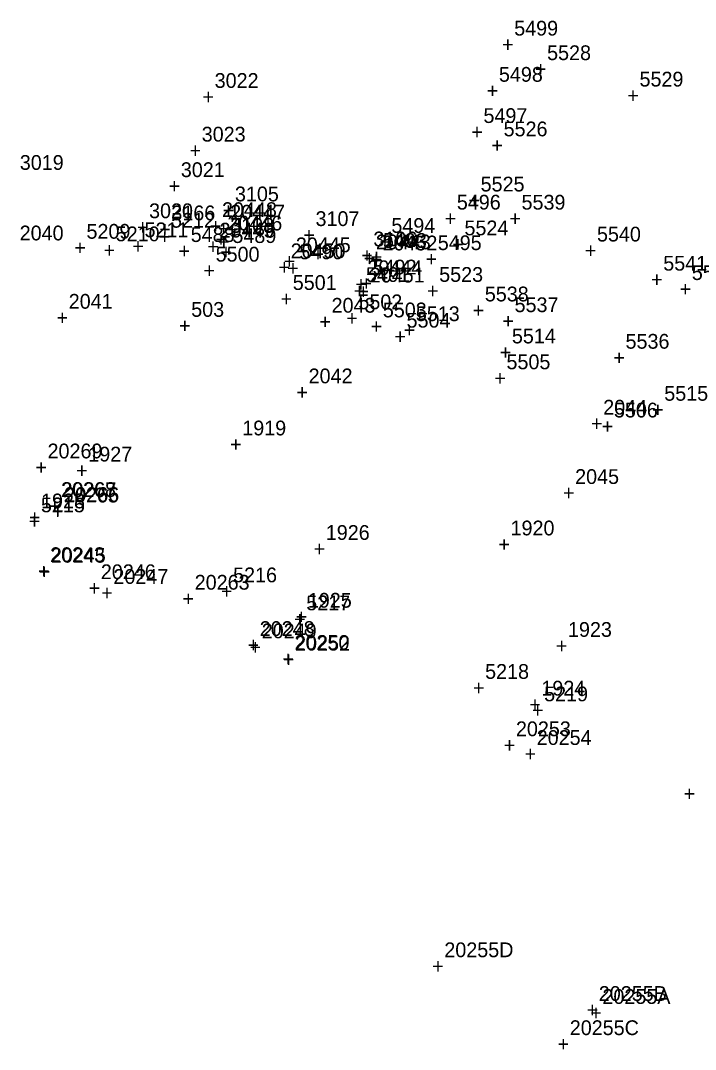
# Model space of a CAD drawing. Extents: x 1036751 to 1042192, y 772604 to 785439.
# Drawn here: x 1041162 to 1041276.4, y 774791.9 to 774966.1 of the extents above; entities that cross this region are included whole.
import ezdxf

# ---------------------------------------------------------------- set-up
doc = ezdxf.new("R2010")
doc.units = 0
for name, color, linetype in [('S_Buildings', 7, 'Continuous'), ('S_Buildings_Attachments', 7, 'Continuous'), ('S_Buildings_SillElevation', 7, 'Continuous'), ('S_Control_Traverse_Point', 7, 'Continuous'), ('S_Curb_Type_1', 7, 'Continuous'), ('S_Curb_Type_2', 7, 'Continuous'), ('S_Drainage_CB', 7, 'Continuous'), ('S_Drainage_Culvert_Top', 7, 'Continuous'), ('S_Drainage_Invert', 7, 'Continuous'), ('S_Drainage_Sump', 7, 'Continuous'), ('S_Fencing_Picket', 7, 'Continuous'), ('S_Ground_LevelString', 7, 'Continuous'), ('S_Property_ConcPad', 7, 'Continuous'), ('S_Property_StoneWall', 7, 'Continuous'), ('S_Roadway_Centerline', 7, 'Continuous'), ('S_Roadway_Edge_Pavement', 7, 'Continuous'), ('S_Roadway_Edge_TW', 7, 'Continuous'), ('S_Traffic_Post_Conc', 7, 'Continuous'), ('S_Traffic_Sign_SinglePost', 7, 'Continuous'), ('S_Trees_Decid_Pay', 7, 'Continuous'), ('S_Utilities_GuyWire3', 7, 'Continuous'), ('S_Utilities_Pole_Power', 7, 'Continuous')]:
    doc.layers.add(name, color=color, linetype=linetype)

msp = doc.modelspace()

# ---------------------------------------------------------------- texts
at = {"layer": 'S_Buildings'}
for s, p in [('3105', (1041198.36, 774935.53)), ('+', (1041196.29, 774932.78)), ('3106', (1041221.81, 774927.9)), ('+', (1041219.75, 774925.15)), ('20243', (1041167.05, 774874.45)), ('+', (1041164.99, 774871.7)), ('20247', (1041177.77, 774870.76)), ('+', (1041175.71, 774868.01)), ('20248', (1041202.56, 774861.94)), ('+', (1041200.5, 774859.19)), ('20254', (1041249.48, 774843.49)), ('+', (1041247.42, 774840.74)), ('20255D', (1041233.83, 774807.55)), ('+', (1041231.77, 774804.8)), ('20255B', (1041260, 774800.15)), ('20255A', (1041260.61, 774799.64)), ('+', (1041257.94, 774797.4)), ('+', (1041258.55, 774796.89)), ('20255C', (1041255.08, 774794.36)), ('+', (1041253.01, 774791.61))]:
    msp.add_text(s, height=2.5, dxfattribs=at).set_placement(p)
at = {"layer": 'S_Buildings_Attachments'}
for s, p in [('20249', (1041202.9, 774861.55)), ('20250', (1041208.45, 774859.59)), ('+', (1041200.84, 774858.8)), ('+', (1041206.39, 774856.84))]:
    msp.add_text(s, height=2.5, dxfattribs=at).set_placement(p)
at = {"layer": 'S_Buildings_SillElevation'}
for s, p in [('3107', (1041212.01, 774931.35)), ('+', (1041209.95, 774928.6))]:
    msp.add_text(s, height=2.5, dxfattribs=at).set_placement(p)
at = {"layer": 'S_Control_Traverse_Point'}
for s, p in [('503', (1041190.95, 774915.98)), ('503', (1041190.95, 774915.98)), ('503', (1041190.95, 774915.98)), ('503', (1041190.95, 774915.98)), ('503', (1041190.95, 774915.98)), ('503', (1041190.95, 774915.98)), ('503', (1041190.95, 774915.98)), ('503', (1041190.95, 774915.98)), ('503', (1041190.95, 774915.98)), ('503', (1041190.95, 774915.98)), ('503', (1041190.95, 774915.98)), ('503', (1041190.95, 774915.98)), ('503', (1041190.95, 774915.98)), ('503', (1041190.95, 774915.98)), ('503', (1041190.95, 774915.98)), ('503', (1041190.95, 774915.98)), ('503', (1041190.95, 774915.98)), ('+', (1041188.89, 774913.23)), ('+', (1041188.89, 774913.23)), ('+', (1041188.89, 774913.23)), ('+', (1041188.89, 774913.23)), ('+', (1041188.89, 774913.23)), ('+', (1041188.89, 774913.23)), ('+', (1041188.89, 774913.23)), ('+', (1041188.89, 774913.23)), ('+', (1041188.89, 774913.23)), ('+', (1041188.89, 774913.23)), ('+', (1041188.89, 774913.23)), ('+', (1041188.89, 774913.23)), ('+', (1041188.89, 774913.23)), ('+', (1041188.89, 774913.23)), ('+', (1041188.89, 774913.23)), ('+', (1041188.89, 774913.23)), ('+', (1041188.89, 774913.23))]:
    msp.add_text(s, height=2.5, dxfattribs=at).set_placement(p)
at = {"layer": 'S_Curb_Type_1'}
for s, p in [('5212', (1041187.52, 774931.07)), ('5209', (1041173.21, 774929.2)), ('5210', (1041178.16, 774928.77)), ('5211', (1041183.04, 774929.45)), ('+', (1041185.46, 774928.32)), ('+', (1041171.15, 774926.45)), ('+', (1041176.1, 774926.02)), ('+', (1041180.98, 774926.7))]:
    msp.add_text(s, height=2.5, dxfattribs=at).set_placement(p)
at = {"layer": 'S_Curb_Type_2'}
for s, p in [('5215', (1041165.49, 774882.88)), ('+', (1041163.43, 774880.13)), ('5216', (1041198.05, 774871.03)), ('+', (1041195.98, 774868.28)), ('5217', (1041210.44, 774866.29)), ('+', (1041208.38, 774863.54)), ('5218', (1041240.74, 774854.68)), ('+', (1041238.68, 774851.93)), ('5219', (1041250.74, 774850.88)), ('+', (1041248.68, 774848.13)), ('+', (1041274.38, 774834.01))]:
    msp.add_text(s, height=2.5, dxfattribs=at).set_placement(p)
at = {"layer": 'S_Drainage_CB'}
for s, p in [('20265', (1041169.39, 774884.54)), ('+', (1041167.33, 774881.79))]:
    msp.add_text(s, height=2.5, dxfattribs=at).set_placement(p)
at = {"layer": 'S_Drainage_Culvert_Top'}
for s, p in [('20269', (1041166.61, 774892.01)), ('+', (1041164.55, 774889.26)), ('20268', (1041168.9, 774885.48)), ('+', (1041166.84, 774882.73))]:
    msp.add_text(s, height=2.5, dxfattribs=at).set_placement(p)
at = {"layer": 'S_Drainage_Invert'}
for s, p in [('20267', (1041168.98, 774885.46)), ('+', (1041166.92, 774882.71))]:
    msp.add_text(s, height=2.5, dxfattribs=at).set_placement(p)
at = {"layer": 'S_Drainage_Sump'}
for s, p in [('20266', (1041169.45, 774884.63)), ('+', (1041167.39, 774881.88))]:
    msp.add_text(s, height=2.5, dxfattribs=at).set_placement(p)
at = {"layer": 'S_Fencing_Picket'}
for s, p in [('20245', (1041167.17, 774874.35)), ('+', (1041165.11, 774871.6)), ('20246', (1041175.64, 774871.56)), ('+', (1041173.58, 774868.81)), ('20252', (1041208.55, 774859.47)), ('+', (1041206.49, 774856.72)), ('20253', (1041245.96, 774844.97)), ('+', (1041243.89, 774842.22))]:
    msp.add_text(s, height=2.5, dxfattribs=at).set_placement(p)
at = {"layer": 'S_Ground_LevelString'}
for s, p in [('5499', (1041245.67, 774963.6)), ('+', (1041243.61, 774960.85)), ('5528', (1041251.24, 774959.44)), ('5498', (1041243.08, 774955.78)), ('+', (1041249.17, 774956.69)), ('5529', (1041266.9, 774954.97)), ('+', (1041241.02, 774953.03)), ('+', (1041264.83, 774952.22)), ('5497', (1041240.46, 774948.8)), ('5526', (1041243.87, 774946.54)), ('+', (1041238.4, 774946.05)), ('+', (1041241.81, 774943.79)), ('5525', (1041239.98, 774937.2)), ('5496', (1041235.95, 774934.14)), ('+', (1041237.92, 774934.45)), ('5539', (1041246.91, 774934.13)), ('20448', (1041196.17, 774932.87)), ('+', (1041233.89, 774931.39)), ('+', (1041244.85, 774931.38)), ('5488', (1041190.86, 774928.65)), ('+', (1041194.11, 774930.12)), ('20449', (1041195.75, 774929.4)), ('5494', (1041224.86, 774930.19)), ('5524', (1041237.24, 774929.78)), ('5540', (1041259.69, 774928.73)), ('5489', (1041197.93, 774928.48)), ('+', (1041222.8, 774927.44)), ('20452', (1041223.36, 774927.22)), ('5493', (1041223.43, 774927.65)), ('5495', (1041232.72, 774927.27)), ('+', (1041188.8, 774925.9)), ('+', (1041193.68, 774926.65)), ('5500', (1041195.09, 774925.33)), ('+', (1041195.87, 774925.73)), ('20450', (1041207.8, 774925.9)), ('5490', (1041209.27, 774925.72)), ('+', (1041235.17, 774927.03)), ('+', (1041257.63, 774925.98)), ('+', (1041221.3, 774924.47)), ('+', (1041221.36, 774924.9)), ('+', (1041230.66, 774924.52)), ('5541', (1041270.92, 774923.8)), ('+', (1041193.03, 774922.58)), ('+', (1041205.74, 774923.15)), ('+', (1041207.2, 774922.97)), ('5491', (1041220.55, 774921.88)), ('20451', (1041221.2, 774921.79)), ('5492', (1041221.69, 774923.15)), ('5523', (1041232.96, 774921.9)), ('5542', (1041275.76, 774922.21)), ('5501', (1041208.15, 774920.53)), ('+', (1041219.63, 774920.41)), ('+', (1041268.86, 774921.05)), ('+', (1041218.48, 774919.13)), ('+', (1041219.14, 774919.04)), ('+', (1041230.9, 774919.15)), ('5538', (1041240.69, 774918.59)), ('+', (1041273.7, 774919.46)), ('+', (1041206.09, 774917.78)), ('5502', (1041219.27, 774917.26)), ('5537', (1041245.73, 774916.77)), ('5503', (1041223.41, 774915.89)), ('5513', (1041229, 774915.25)), ('+', (1041238.63, 774915.84)), ('+', (1041217.21, 774914.51)), ('5504', (1041227.43, 774914.15)), ('+', (1041243.67, 774914.02)), ('+', (1041221.35, 774913.14)), ('+', (1041226.94, 774912.5)), ('5514', (1041245.28, 774911.48)), ('+', (1041225.37, 774911.4)), ('5536', (1041264.53, 774910.58)), ('+', (1041243.22, 774908.73)), ('5505', (1041244.36, 774907.1)), ('+', (1041262.47, 774907.83)), ('+', (1041242.3, 774904.35)), ('5515', (1041271.09, 774901.77)), ('5506', (1041262.56, 774898.94)), ('+', (1041269.03, 774899.02)), ('+', (1041260.5, 774896.19))]:
    msp.add_text(s, height=2.5, dxfattribs=at).set_placement(p)
at = {"layer": 'S_Property_ConcPad'}
for s, p in [('20447', (1041197.55, 774932.44)), ('20446', (1041197.08, 774930.6)), ('+', (1041195.49, 774929.69)), ('+', (1041195.02, 774927.85)), ('20445', (1041208.67, 774926.91)), ('20443', (1041222.23, 774927.41)), ('+', (1041206.61, 774924.16)), ('+', (1041220.17, 774924.66)), ('20444', (1041220.8, 774923.03)), ('+', (1041218.74, 774920.28))]:
    msp.add_text(s, height=2.5, dxfattribs=at).set_placement(p)
at = {"layer": 'S_Property_StoneWall'}
for s, p in [('3022', (1041194.92, 774954.74)), ('+', (1041192.86, 774951.99)), ('3021', (1041189.19, 774939.64)), ('+', (1041187.13, 774936.89)), ('3020', (1041183.81, 774932.68)), ('+', (1041181.75, 774929.93))]:
    msp.add_text(s, height=2.5, dxfattribs=at).set_placement(p)
at = {"layer": 'S_Roadway_Centerline'}
for s, p in [('1919', (1041199.6, 774895.9)), ('+', (1041197.54, 774893.15)), ('1920', (1041245.05, 774878.97)), ('+', (1041242.99, 774876.22))]:
    msp.add_text(s, height=2.5, dxfattribs=at).set_placement(p)
at = {"layer": 'S_Roadway_Edge_Pavement'}
for s, p in [('2040', (1041161.89, 774928.92)), ('2043', (1041214.73, 774916.68)), ('+', (1041212.67, 774913.93)), ('2044', (1041260.75, 774899.42)), ('+', (1041258.68, 774896.67)), ('1928', (1041165.51, 774883.55)), ('+', (1041163.45, 774880.8)), ('1925', (1041210.71, 774866.73)), ('+', (1041208.65, 774863.98)), ('1924', (1041250.27, 774851.85)), ('+', (1041248.21, 774849.1))]:
    msp.add_text(s, height=2.5, dxfattribs=at).set_placement(p)
at = {"layer": 'S_Roadway_Edge_TW'}
for s, p in [('2041', (1041170.2, 774917.35)), ('+', (1041168.14, 774914.6)), ('2042', (1041210.84, 774904.72)), ('+', (1041208.77, 774901.97)), ('1927', (1041173.51, 774891.48)), ('+', (1041171.44, 774888.73)), ('2045', (1041255.99, 774887.68)), ('+', (1041253.93, 774884.93)), ('1926', (1041213.75, 774878.21)), ('+', (1041211.69, 774875.46)), ('1923', (1041254.78, 774861.79)), ('+', (1041252.72, 774859.04))]:
    msp.add_text(s, height=2.5, dxfattribs=at).set_placement(p)
at = {"layer": 'S_Traffic_Post_Conc'}
for s, p in [('3108', (1041197.56, 774930.19)), ('+', (1041195.5, 774927.44))]:
    msp.add_text(s, height=2.5, dxfattribs=at).set_placement(p)
at = {"layer": 'S_Traffic_Sign_SinglePost'}
for s, p in [('20263', (1041191.54, 774869.78)), ('+', (1041189.48, 774867.03))]:
    msp.add_text(s, height=2.5, dxfattribs=at).set_placement(p)
at = {"layer": 'S_Trees_Decid_Pay'}
msp.add_text('3019', height=2.5, dxfattribs=at).set_placement((1041161.91, 774940.86))
at = {"layer": 'S_Utilities_GuyWire3'}
for s, p in [('3023', (1041192.73, 774945.65)), ('+', (1041190.67, 774942.9))]:
    msp.add_text(s, height=2.5, dxfattribs=at).set_placement(p)
at = {"layer": 'S_Utilities_Pole_Power'}
for s, p in [('3166', (1041187.59, 774932.32)), ('+', (1041185.53, 774929.57))]:
    msp.add_text(s, height=2.5, dxfattribs=at).set_placement(p)

doc.saveas('drawing.dxf')
